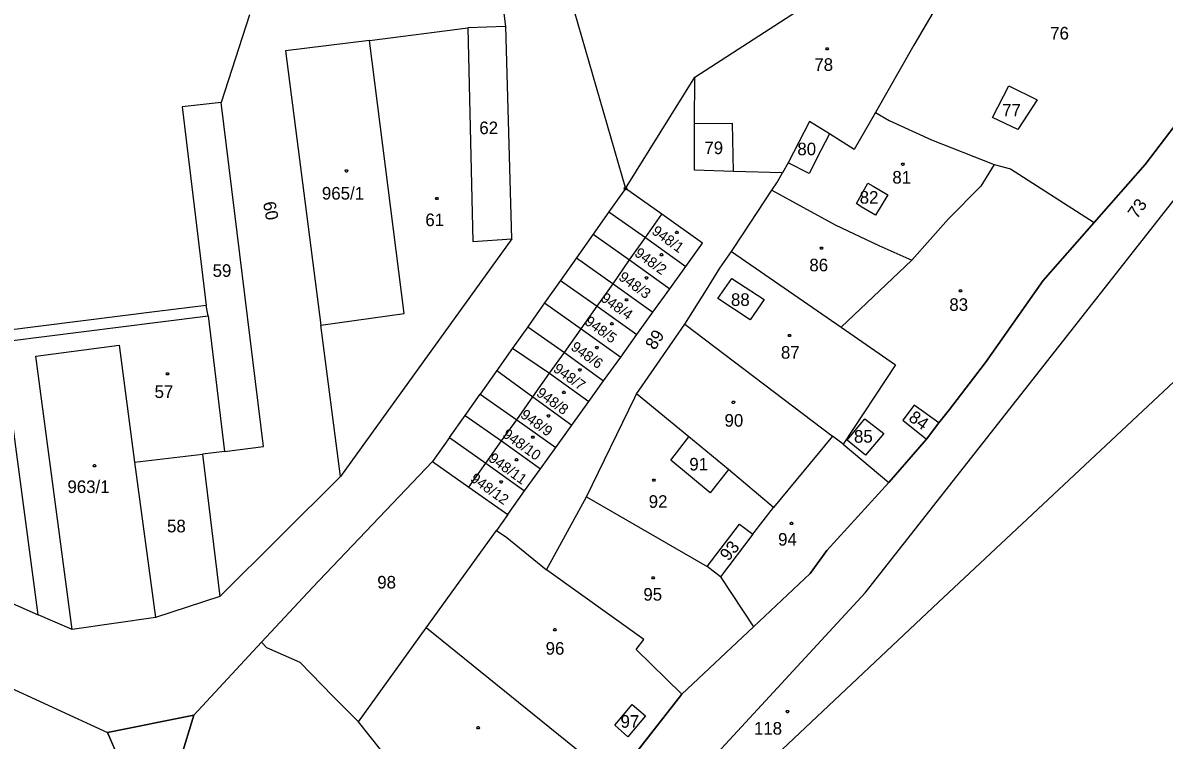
# Model space of a CAD drawing. Extents: x -841286 to -834997, y -1020681 to -1017810.
# Drawn here: x -838539 to -838385, y -1019270.6 to -1019173.8 of the extents above; entities that cross this region are included whole.
import ezdxf

# ---------------------------------------------------------------- set-up
doc = ezdxf.new("R2010")
doc.units = 0
for name, color, linetype in [('NERES_HRA', 7, 'Continuous'), ('OVNE_POP', 7, 'Continuous'), ('OVNE_PRE', 7, 'Continuous'), ('OVNE_SET', 7, 'Continuous'), ('OVNI_PRE', 7, 'Continuous'), ('OVNI_SET', 7, 'Continuous')]:
    doc.layers.add(name, color=color, linetype=linetype)

msp = doc.modelspace()

# ---------------------------------------------------------------- linework, layer by layer
at = {"layer": 'NERES_HRA'}
msp.add_lwpolyline([(-838457.62, -1019196), (-838457.53, -1019196.15), (-838457.62, -1019196.3), (-838457.8, -1019196.3), (-838457.89, -1019196.15), (-838457.8, -1019196)], close=True, dxfattribs=at)
at = {"layer": 'OVNE_POP'}
for points in [[(-838430.42, -1019177.13), (-838430.33, -1019177.28), (-838430.42, -1019177.43), (-838430.6, -1019177.43), (-838430.69, -1019177.28), (-838430.6, -1019177.13)], [(-838420.18, -1019192.71), (-838420.09, -1019192.86), (-838420.18, -1019193.01), (-838420.36, -1019193.01), (-838420.45, -1019192.86), (-838420.36, -1019192.71)], [(-838483.09, -1019197.34), (-838483, -1019197.49), (-838483.09, -1019197.64), (-838483.27, -1019197.64), (-838483.36, -1019197.49), (-838483.27, -1019197.34)], [(-838431.18, -1019204.03), (-838431.09, -1019204.18), (-838431.18, -1019204.33), (-838431.36, -1019204.33), (-838431.45, -1019204.18), (-838431.36, -1019204.03)], [(-838412.4, -1019209.79), (-838412.31, -1019209.94), (-838412.4, -1019210.09), (-838412.58, -1019210.09), (-838412.67, -1019209.94), (-838412.58, -1019209.79)], [(-838435.46, -1019215.82), (-838435.37, -1019215.97), (-838435.46, -1019216.12), (-838435.64, -1019216.12), (-838435.73, -1019215.97), (-838435.64, -1019215.82)], [(-838519.42, -1019220.99), (-838519.33, -1019221.14), (-838519.42, -1019221.29), (-838519.6, -1019221.29), (-838519.69, -1019221.14), (-838519.6, -1019220.99)], [(-838443.06, -1019224.83), (-838442.97, -1019224.98), (-838443.06, -1019225.13), (-838443.24, -1019225.13), (-838443.33, -1019224.98), (-838443.24, -1019224.83)], [(-838453.79, -1019235.35), (-838453.7, -1019235.5), (-838453.79, -1019235.65), (-838453.97, -1019235.65), (-838454.06, -1019235.5), (-838453.97, -1019235.35)], [(-838435.22, -1019241.18), (-838435.13, -1019241.33), (-838435.22, -1019241.48), (-838435.4, -1019241.48), (-838435.49, -1019241.33), (-838435.4, -1019241.18)], [(-838453.88, -1019248.53), (-838453.79, -1019248.68), (-838453.88, -1019248.83), (-838454.06, -1019248.83), (-838454.15, -1019248.68), (-838454.06, -1019248.53)], [(-838467.14, -1019255.53), (-838467.05, -1019255.68), (-838467.14, -1019255.83), (-838467.32, -1019255.83), (-838467.41, -1019255.68), (-838467.32, -1019255.53)], [(-838435.77, -1019266.58), (-838435.68, -1019266.73), (-838435.77, -1019266.88), (-838435.95, -1019266.88), (-838436.04, -1019266.73), (-838435.95, -1019266.58)], [(-838477.49, -1019268.76), (-838477.4, -1019268.91), (-838477.49, -1019269.06), (-838477.67, -1019269.06), (-838477.76, -1019268.91), (-838477.67, -1019268.76)]]:
    msp.add_lwpolyline(points, close=True, dxfattribs=at)
at = {"layer": 'OVNE_SET'}
for p, q in [((-838448.35, -1019181.12), (-838408.56, -1019155.36)), ((-838473.87, -1019174.25), (-838475.59, -1019160.51)), ((-838412.17, -1019165.43), (-838418.77, -1019176.81)), ((-838508.43, -1019172.69), (-838512.25, -1019184.55)), ((-838464.64, -1019172.19), (-838457.71, -1019196.15)), ((-838492.25, -1019176.15), (-838479, -1019174.45)), ((-838473.87, -1019174.25), (-838479, -1019174.45)), ((-838479, -1019174.45), (-838478.31, -1019203.27)), ((-838473.03, -1019202.95), (-838473.87, -1019174.25)), ((-838492.25, -1019176.15), (-838503.6, -1019177.55)), ((-838487.58, -1019213.02), (-838492.25, -1019176.15)), ((-838503.6, -1019177.55), (-838498.83, -1019214.6)), ((-838418.77, -1019176.81), (-838423.98, -1019185.9)), ((-838457.71, -1019196.15), (-838448.35, -1019181.12)), ((-838448.37, -1019187.4), (-838448.35, -1019181.12)), ((-838408.18, -1019186.54), (-838405.99, -1019182.29)), ((-838405.99, -1019182.29), (-838402.17, -1019184.15)), ((-838402.17, -1019184.15), (-838404.75, -1019188.19)), ((-838512.25, -1019184.55), (-838517.52, -1019185.13)), ((-838517.52, -1019185.13), (-838514.27, -1019211.93)), ((-838506.54, -1019230.97), (-838512.25, -1019184.55)), ((-838432.85, -1019187.11), (-838435.77, -1019192.66)), ((-838430.19, -1019188.77), (-838432.85, -1019187.11)), ((-838423.98, -1019185.9), (-838426.84, -1019190.86)), ((-838423.98, -1019185.9), (-838422.13, -1019186.95)), ((-838422.13, -1019186.95), (-838416.4, -1019189.57)), ((-838404.75, -1019188.19), (-838408.18, -1019186.54)), ((-838382.22, -1019185.88), (-838387.57, -1019192.9)), ((-838448.39, -1019193.68), (-838448.37, -1019187.4)), ((-838443.27, -1019187.37), (-838448.37, -1019187.4)), ((-838443.15, -1019193.82), (-838443.27, -1019187.37)), ((-838430.19, -1019188.77), (-838431.32, -1019190.99)), ((-838426.84, -1019190.86), (-838430.19, -1019188.77)), ((-838416.4, -1019189.57), (-838407.96, -1019192.89)), ((-838431.32, -1019190.99), (-838432.93, -1019194.12)), ((-838435.77, -1019192.66), (-838436.52, -1019194)), ((-838432.93, -1019194.12), (-838435.77, -1019192.66)), ((-838407.96, -1019192.89), (-838409.74, -1019195.81)), ((-838407.96, -1019192.89), (-838405.75, -1019193.47)), ((-838387.57, -1019192.9), (-838394.45, -1019200.72)), ((-838443.15, -1019193.82), (-838448.39, -1019193.68)), ((-838436.52, -1019194), (-838443.15, -1019193.82)), ((-838437.29, -1019195.39), (-838436.52, -1019194)), ((-838405.75, -1019193.47), (-838394.45, -1019200.72)), ((-838457.71, -1019196.15), (-838459.93, -1019199.29)), ((-838452.82, -1019199.6), (-838457.71, -1019196.15)), ((-838441.83, -1019202.24), (-838437.95, -1019196.38)), ((-838437.95, -1019196.38), (-838437.29, -1019195.39)), ((-838437.95, -1019196.38), (-838429.42, -1019201.05)), ((-838426.55, -1019198.18), (-838424.99, -1019195.42)), ((-838424.99, -1019195.42), (-838424.27, -1019195.81)), ((-838424.27, -1019195.81), (-838422.29, -1019197)), ((-838409.74, -1019195.81), (-838414.11, -1019200.25)), ((-838425.35, -1019250.72), (-838383.36, -1019197.26)), ((-838422.29, -1019197), (-838423.96, -1019199.74)), ((-838459.93, -1019199.29), (-838462.06, -1019202.3)), ((-838459.93, -1019199.29), (-838455.02, -1019202.73)), ((-838447.3, -1019203.5), (-838452.82, -1019199.6)), ((-838425.88, -1019198.61), (-838426.55, -1019198.18)), ((-838423.96, -1019199.74), (-838425.88, -1019198.61)), ((-838429.42, -1019201.05), (-838423.51, -1019203.84)), ((-838414.11, -1019200.25), (-838419.04, -1019205.8)), ((-838394.45, -1019200.72), (-838401.33, -1019208.53)), ((-838462.06, -1019202.3), (-838464.33, -1019205.5)), ((-838462.06, -1019202.3), (-838457.14, -1019205.76)), ((-838443.41, -1019204.65), (-838441.83, -1019202.24)), ((-838473.03, -1019202.95), (-838496.17, -1019234.99)), ((-838478.31, -1019203.27), (-838473.03, -1019202.95)), ((-838455.02, -1019202.73), (-838449.57, -1019206.67)), ((-838449.57, -1019206.67), (-838447.3, -1019203.5)), ((-838423.51, -1019203.84), (-838419.04, -1019205.8)), ((-838464.33, -1019205.5), (-838466.47, -1019208.53)), ((-838464.33, -1019205.5), (-838459.36, -1019208.99)), ((-838457.14, -1019205.76), (-838451.73, -1019209.67)), ((-838444.97, -1019206.89), (-838443.41, -1019204.65)), ((-838443.41, -1019204.65), (-838428.59, -1019214.87)), ((-838451.73, -1019209.67), (-838449.57, -1019206.67)), ((-838446.78, -1019209.81), (-838444.97, -1019206.89)), ((-838419.04, -1019205.8), (-838428.59, -1019214.87)), ((-838466.47, -1019208.53), (-838468.62, -1019211.58)), ((-838466.47, -1019208.53), (-838461.51, -1019212.01)), ((-838445.24, -1019210.97), (-838443.37, -1019208.3)), ((-838443.37, -1019208.3), (-838439.01, -1019211.1)), ((-838401.33, -1019208.53), (-838403.7, -1019211.86)), ((-838459.36, -1019208.99), (-838454, -1019212.84)), ((-838454, -1019212.84), (-838451.73, -1019209.67)), ((-838449.71, -1019214.45), (-838446.78, -1019209.81)), ((-838514.27, -1019211.93), (-838520.89, -1019212.74)), ((-838514.04, -1019213.3), (-838514.27, -1019211.93)), ((-838468.62, -1019211.58), (-838470.9, -1019214.82)), ((-838468.62, -1019211.58), (-838463.67, -1019215.06)), ((-838440.86, -1019213.85), (-838445.24, -1019210.97)), ((-838439.01, -1019211.1), (-838440.86, -1019213.85)), ((-838403.7, -1019211.86), (-838409.1, -1019219.62)), ((-838520.89, -1019212.74), (-838541.6, -1019215.35)), ((-838520.8, -1019214.17), (-838514.04, -1019213.3)), ((-838514.04, -1019213.3), (-838511.83, -1019231.61)), ((-838498.83, -1019214.6), (-838487.58, -1019213.02)), ((-838461.51, -1019212.01), (-838456.16, -1019215.84)), ((-838456.16, -1019215.84), (-838454, -1019212.84)), ((-838540.79, -1019216.68), (-838520.8, -1019214.17)), ((-838496.17, -1019234.99), (-838498.83, -1019214.6)), ((-838470.9, -1019214.82), (-838472.94, -1019217.69)), ((-838470.9, -1019214.82), (-838465.95, -1019218.28)), ((-838455.87, -1019223.36), (-838449.71, -1019214.45)), ((-838449.71, -1019214.45), (-838429.76, -1019229.55)), ((-838428.59, -1019214.87), (-838421.25, -1019219.94)), ((-838463.67, -1019215.06), (-838458.35, -1019218.89)), ((-838458.35, -1019218.89), (-838456.16, -1019215.84)), ((-838537.27, -1019218.77), (-838526.05, -1019217.29)), ((-838526.05, -1019217.29), (-838523.94, -1019233.07)), ((-838472.94, -1019217.69), (-838475.05, -1019220.68)), ((-838472.94, -1019217.69), (-838467.95, -1019221.07)), ((-838532.36, -1019255.66), (-838537.27, -1019218.77)), ((-838465.95, -1019218.28), (-838460.65, -1019222.09)), ((-838460.65, -1019222.09), (-838458.35, -1019218.89)), ((-838416.24, -1019252.7), (-838380.62, -1019219.32)), ((-838409.1, -1019219.62), (-838413.97, -1019225.98)), ((-838536.94, -1019253.66), (-838541.4, -1019220.14)), ((-838475.05, -1019220.68), (-838477.3, -1019223.87)), ((-838475.05, -1019220.68), (-838470.21, -1019224.27)), ((-838467.95, -1019221.07), (-838462.66, -1019224.9)), ((-838421.25, -1019219.94), (-838428.32, -1019230.64)), ((-838462.66, -1019224.9), (-838460.65, -1019222.09)), ((-838479.35, -1019226.76), (-838477.3, -1019223.87)), ((-838477.3, -1019223.87), (-838472.37, -1019227.34)), ((-838456.46, -1019224.36), (-838456.22, -1019223.86)), ((-838456.22, -1019223.86), (-838455.87, -1019223.36)), ((-838449.16, -1019229.65), (-838456.22, -1019223.86)), ((-838470.21, -1019224.27), (-838464.93, -1019228.06)), ((-838464.93, -1019228.06), (-838462.66, -1019224.9)), ((-838462.97, -1019237.73), (-838456.46, -1019224.36)), ((-838418.73, -1019225.36), (-838420.26, -1019227.38)), ((-838415.43, -1019227.74), (-838418.73, -1019225.36)), ((-838481.47, -1019229.74), (-838479.35, -1019226.76)), ((-838479.35, -1019226.76), (-838474.44, -1019230.21)), ((-838472.37, -1019227.34), (-838467.12, -1019231.11)), ((-838427.8, -1019230.08), (-838425.4, -1019227.2)), ((-838425.4, -1019227.2), (-838422.85, -1019229.18)), ((-838413.97, -1019225.98), (-838415.43, -1019227.74)), ((-838467.12, -1019231.11), (-838464.93, -1019228.06)), ((-838420.26, -1019227.38), (-838417.07, -1019229.95)), ((-838415.43, -1019227.74), (-838417.07, -1019229.95)), ((-838481.47, -1019229.74), (-838483.75, -1019232.98)), ((-838481.47, -1019229.74), (-838476.56, -1019233.2)), ((-838474.44, -1019230.21), (-838469.19, -1019233.99)), ((-838451.58, -1019232.78), (-838449.16, -1019229.65)), ((-838443.78, -1019234.08), (-838449.16, -1019229.65)), ((-838429.76, -1019229.55), (-838437.73, -1019239.18)), ((-838428.32, -1019230.64), (-838429.76, -1019229.55)), ((-838425.32, -1019232.14), (-838427.8, -1019230.08)), ((-838422.85, -1019229.18), (-838425.32, -1019232.14)), ((-838417.07, -1019229.95), (-838422.15, -1019235.8)), ((-838523.94, -1019233.07), (-838514.8, -1019231.97)), ((-838511.83, -1019231.61), (-838514.8, -1019231.97)), ((-838514.8, -1019231.97), (-838512.43, -1019251.2)), ((-838511.83, -1019231.61), (-838506.54, -1019230.97)), ((-838469.19, -1019233.99), (-838467.12, -1019231.11)), ((-838428.32, -1019230.64), (-838422.15, -1019235.8)), ((-838523.94, -1019233.07), (-838521.14, -1019254.03)), ((-838499.96, -1019249.99), (-838483.75, -1019232.98)), ((-838483.75, -1019232.98), (-838478.84, -1019236.43)), ((-838476.56, -1019233.2), (-838471.32, -1019236.95)), ((-838446.28, -1019237.19), (-838451.58, -1019232.78)), ((-838512.43, -1019251.2), (-838496.17, -1019234.99)), ((-838471.32, -1019236.95), (-838469.19, -1019233.99)), ((-838443.78, -1019234.08), (-838446.28, -1019237.19)), ((-838437.73, -1019239.18), (-838443.78, -1019234.08)), ((-838478.84, -1019236.43), (-838473.59, -1019240.12)), ((-838422.15, -1019235.8), (-838430.53, -1019244.98)), ((-838473.59, -1019240.12), (-838471.32, -1019236.95)), ((-838468.36, -1019247.6), (-838462.97, -1019237.73)), ((-838462.97, -1019237.73), (-838446.7, -1019247.15)), ((-838440.54, -1019242.8), (-838437.73, -1019239.18)), ((-838473.59, -1019240.12), (-838475.09, -1019242.27)), ((-838484.58, -1019255.43), (-838475.09, -1019242.27)), ((-838475.09, -1019242.27), (-838473.71, -1019243.24)), ((-838446.7, -1019247.15), (-838442.31, -1019241.44)), ((-838442.31, -1019241.44), (-838440.54, -1019242.8)), ((-838473.71, -1019243.24), (-838468.36, -1019247.6)), ((-838440.54, -1019242.8), (-838444.9, -1019248.56)), ((-838430.53, -1019244.98), (-838432.78, -1019248.08)), ((-838444.9, -1019248.56), (-838446.7, -1019247.15)), ((-838574.9, -1019247.75), (-838527.61, -1019269.56)), ((-838548.51, -1019248.6), (-838536.94, -1019253.66)), ((-838455.22, -1019256.98), (-838468.36, -1019247.6)), ((-838444.9, -1019248.56), (-838440.44, -1019255.3)), ((-838432.78, -1019248.08), (-838440.44, -1019255.3)), ((-838506.82, -1019257.37), (-838499.96, -1019249.99)), ((-838512.43, -1019251.2), (-838521.14, -1019254.03)), ((-838466.36, -1019295.07), (-838425.35, -1019250.72)), ((-838479.91, -1019312.64), (-838416.24, -1019252.7)), ((-838532.36, -1019255.66), (-838536.94, -1019253.66)), ((-838521.14, -1019254.03), (-838532.36, -1019255.66)), ((-838493.71, -1019268.09), (-838484.58, -1019255.43)), ((-838459.17, -1019275.97), (-838484.58, -1019255.43)), ((-838440.44, -1019255.3), (-838450.12, -1019264.38)), ((-838515.97, -1019267.23), (-838506.82, -1019257.37)), ((-838506.11, -1019258.12), (-838506.82, -1019257.37)), ((-838501.62, -1019260.12), (-838506.11, -1019258.12)), ((-838456.24, -1019258.36), (-838455.22, -1019256.98)), ((-838450.12, -1019264.38), (-838456.24, -1019258.36)), ((-838497.18, -1019264.64), (-838501.62, -1019260.12)), ((-838493.71, -1019268.09), (-838497.18, -1019264.64)), ((-838450.12, -1019264.38), (-838459.17, -1019275.97)), ((-838459.13, -1019268.57), (-838456.82, -1019265.77)), ((-838456.82, -1019265.77), (-838455.01, -1019267.28)), ((-838515.97, -1019267.23), (-838527.61, -1019269.56)), ((-838517.7, -1019272.98), (-838515.97, -1019267.23)), ((-838455.01, -1019267.28), (-838457.39, -1019270.13)), ((-838486.87, -1019276.7), (-838493.71, -1019268.09)), ((-838457.39, -1019270.13), (-838459.13, -1019268.57)), ((-838527.61, -1019269.56), (-838521.36, -1019283.94))]:
    msp.add_line(p, q, dxfattribs=at)
at = {"layer": 'OVNI_PRE'}
for points in [[(-838495.28, -1019193.61), (-838495.19, -1019193.76), (-838495.28, -1019193.91), (-838495.46, -1019193.91), (-838495.55, -1019193.76), (-838495.46, -1019193.61)], [(-838450.67, -1019201.91), (-838450.58, -1019202.06), (-838450.67, -1019202.21), (-838450.85, -1019202.21), (-838450.94, -1019202.06), (-838450.85, -1019201.91)], [(-838452.75, -1019204.92), (-838452.66, -1019205.07), (-838452.75, -1019205.22), (-838452.93, -1019205.22), (-838453.02, -1019205.07), (-838452.93, -1019204.92)], [(-838454.76, -1019208.05), (-838454.67, -1019208.2), (-838454.76, -1019208.35), (-838454.94, -1019208.35), (-838455.03, -1019208.2), (-838454.94, -1019208.05)], [(-838457.48, -1019211.01), (-838457.39, -1019211.16), (-838457.48, -1019211.31), (-838457.66, -1019211.31), (-838457.75, -1019211.16), (-838457.66, -1019211.01)], [(-838459.45, -1019214.24), (-838459.36, -1019214.39), (-838459.45, -1019214.54), (-838459.63, -1019214.54), (-838459.72, -1019214.39), (-838459.63, -1019214.24)], [(-838461.46, -1019217.46), (-838461.37, -1019217.61), (-838461.46, -1019217.76), (-838461.64, -1019217.76), (-838461.73, -1019217.61), (-838461.64, -1019217.46)], [(-838463.76, -1019220.47), (-838463.67, -1019220.62), (-838463.76, -1019220.77), (-838463.94, -1019220.77), (-838464.03, -1019220.62), (-838463.94, -1019220.47)], [(-838465.93, -1019223.5), (-838465.84, -1019223.65), (-838465.93, -1019223.8), (-838466.11, -1019223.8), (-838466.2, -1019223.65), (-838466.11, -1019223.5)], [(-838467.99, -1019226.68), (-838467.9, -1019226.83), (-838467.99, -1019226.98), (-838468.17, -1019226.98), (-838468.26, -1019226.83), (-838468.17, -1019226.68)], [(-838470.13, -1019229.54), (-838470.04, -1019229.69), (-838470.13, -1019229.84), (-838470.31, -1019229.84), (-838470.4, -1019229.69), (-838470.31, -1019229.54)], [(-838529.29, -1019233.4), (-838529.2, -1019233.55), (-838529.29, -1019233.7), (-838529.47, -1019233.7), (-838529.56, -1019233.55), (-838529.47, -1019233.4)], [(-838472.31, -1019232.59), (-838472.22, -1019232.74), (-838472.31, -1019232.89), (-838472.49, -1019232.89), (-838472.58, -1019232.74), (-838472.49, -1019232.59)], [(-838474.41, -1019235.58), (-838474.32, -1019235.73), (-838474.41, -1019235.88), (-838474.59, -1019235.88), (-838474.68, -1019235.73), (-838474.59, -1019235.58)]]:
    msp.add_lwpolyline(points, close=True, dxfattribs=at)
at = {"layer": 'OVNI_SET'}
for p, q in [((-838455.02, -1019202.73), (-838452.82, -1019199.6)), ((-838457.14, -1019205.76), (-838455.02, -1019202.73)), ((-838459.36, -1019208.99), (-838457.14, -1019205.76)), ((-838461.51, -1019212.01), (-838459.36, -1019208.99)), ((-838463.67, -1019215.06), (-838461.51, -1019212.01)), ((-838465.95, -1019218.28), (-838463.67, -1019215.06)), ((-838467.95, -1019221.07), (-838465.95, -1019218.28)), ((-838470.21, -1019224.27), (-838467.95, -1019221.07)), ((-838472.37, -1019227.34), (-838470.21, -1019224.27)), ((-838474.44, -1019230.21), (-838472.37, -1019227.34)), ((-838476.56, -1019233.2), (-838474.44, -1019230.21)), ((-838478.84, -1019236.43), (-838476.56, -1019233.2))]:
    msp.add_line(p, q, dxfattribs=at)
for points in [[(-838459.17, -1019275.97), (-838450.12, -1019264.38), (-838440.44, -1019255.3), (-838432.78, -1019248.08), (-838430.53, -1019244.98), (-838422.15, -1019235.8), (-838417.07, -1019229.95), (-838415.43, -1019227.74), (-838413.97, -1019225.98), (-838409.1, -1019219.62), (-838403.7, -1019211.86), (-838401.33, -1019208.53), (-838394.45, -1019200.72), (-838387.57, -1019192.9), (-838382.22, -1019185.88)], [(-838521.36, -1019283.94), (-838527.61, -1019269.56), (-838515.97, -1019267.23), (-838517.7, -1019272.98)]]:
    msp.add_lwpolyline(points, dxfattribs=at)

# ---------------------------------------------------------------- texts
at = {"layer": 'OVNE_PRE'}
for s, p in [('76', (-838400.39, -1019176.03)), ('78', (-838432.22, -1019180.26)), ('77', (-838406.87, -1019186.41)), ('62', (-838477.43, -1019188.8)), ('79', (-838447.06, -1019191.5)), ('80', (-838434.51, -1019191.65)), ('81', (-838421.69, -1019195.47)), ('965/1', (-838498.67, -1019197.63)), ('82', (-838426.1, -1019198.18)), ('61', (-838484.71, -1019201.21)), ('86', (-838432.89, -1019207.31)), ('59', (-838513.42, -1019208.06)), ('88', (-838443.47, -1019211.98)), ('83', (-838414, -1019212.65)), ('87', (-838436.73, -1019219.1)), ('57', (-838521.25, -1019224.41)), ('90', (-838444.34, -1019228.28)), ('85', (-838426.87, -1019230.44)), ('91', (-838449.09, -1019234.19)), ('963/1', (-838533.01, -1019237.23)), ('92', (-838454.57, -1019239.23)), ('58', (-838519.57, -1019242.54)), ('94', (-838437.11, -1019244.33)), ('98', (-838491.2, -1019250.12)), ('95', (-838455.29, -1019251.76)), ('96', (-838468.48, -1019259.05)), ('97', (-838458.37, -1019268.91)), ('118', (-838440.37, -1019269.84))]:
    msp.add_text(s, height=1.7, dxfattribs=at).set_placement(p)
for s, height, rotation, p in [('60', 1.7, 280.8639, (-838506.64, -1019198.05)), ('73', 1.7, 55.5196, (-838388.66, -1019200.35)), ('948/1', 1.4, 324.1795, (-838454.27, -1019202.16)), ('948/2', 1.4, 324.1795, (-838456.6, -1019205.13)), ('948/3', 1.4, 324.1795, (-838458.74, -1019208.36)), ('948/4', 1.4, 324.1795, (-838461.17, -1019211.21)), ('948/5', 1.4, 324.1795, (-838463.33, -1019214.36)), ('89', 1.7, 57.1812, (-838453.74, -1019218.04)), ('948/6', 1.4, 324.1795, (-838465.19, -1019217.8)), ('948/7', 1.4, 324.1795, (-838467.56, -1019220.73)), ('948/8', 1.4, 324.1795, (-838469.85, -1019224.01)), ('948/9', 1.4, 324.1795, (-838472, -1019226.94)), ('84', 1.7, 324.9817, (-838419.63, -1019227.38)), ('948/10', 1.4, 324.1795, (-838474.41, -1019229.57)), ('948/11', 1.4, 324.1795, (-838476.3, -1019232.82)), ('948/12', 1.4, 324.1795, (-838478.75, -1019235.55)), ('93', 1.7, 50.4203, (-838443.82, -1019246.52))]:
    msp.add_text(s, height=height, rotation=rotation, dxfattribs=at).set_placement(p)

doc.saveas('drawing.dxf')
